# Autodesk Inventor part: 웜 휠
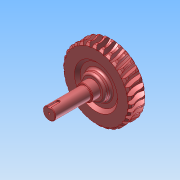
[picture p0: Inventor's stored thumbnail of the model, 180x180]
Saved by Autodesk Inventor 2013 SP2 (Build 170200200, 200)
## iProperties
Created: 2025-06
Part Number: 웜 휠
Material: Generic
Document SubType Name: Modeling
Designer: a
Density: 1 g/cm^3
Author: a
변환 표준: STEP AP214IS
전처리기: Build: 200, Release: 2013 SP2 Update 6 - Date: Thu 07/17/2014
전송 단위: 밀리미터
불확실성: 0.01
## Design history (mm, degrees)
node "웜 휠1"
body "Solid1"
node "기준1"
